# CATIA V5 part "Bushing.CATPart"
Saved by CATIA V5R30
Part number: Bushing
Bounding box of the stored display mesh (mm): x -13.45 to 13.45, y 0 to 63, z -13.45 to 13.45
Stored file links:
  D:\PROJECTS\CATIA V56R 2020\Resources\Parts File\c14_catia_v5_6r2020_prt\c14-catia-v5-6r2020-figr-14-26 & 27\Part & Asm\Bushing.CATPart
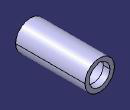
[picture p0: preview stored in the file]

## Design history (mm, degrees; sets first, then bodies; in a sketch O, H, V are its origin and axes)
Body1 (main body)
  Sketch1 on zx-plane, origin (0, 0, 0), H (-1, 0, 0), V (0, 0, 1)
    circle A1 centre (0, 0) radius 9.5
    circle A2 centre (0, 0) radius 13.45
    radius A1 = 9.5
    radius A2 = 13.45
  Pad1: profile Sketch1, direction (0, 1, 0), length 63
  Sketch2 on face of Pad1, origin (0, 63, 0), H (-1, 0, 0), V (0, 0, 1)
    line L1 (-1.5, 9.3808) -> (1.5, 9.3808)
    line L2 (1.5, 9.3808) -> (1.5, 10.1808)
    line L3 (1.5, 10.1808) -> (-1.5, 10.1808)
    line L4 (-1.5, 10.1808) -> (-1.5, 9.3808)
    point P2 (1.5, 9.3808)
    reference projected circle E1 centre (0, 0) radius 9.5 from edge of Pad1
    length L3 = 3
    length L2 = 0.8
    distance V L4 = 1.5
    horizontal: L1 H, L3 H
    vertical: L2 V, L4 V
    coincidence: P2 E1
  Pocket1: profile Sketch2, direction (0, -1, 0), through (limit type 6)
  Sketch3 on xy-plane, origin (0, 0, 0), H (1, 0, 0), V (0, 1, 0)
    line L1 (9.5, 57) -> (10.3, 57)
    line L2 (10.3, 57) -> (10.3, 49)
    line L3 (10.3, 49) -> (9.5, 49)
    line L4 (9.5, 49) -> (9.5, 57)
    reference projected line E1 (13.45, 63) -> (-13.45, 63) from edge of Pad1
    length L2 = 8
    length L1 = 0.8
    distance L3 E1 = 14
    distance V L4 = 9.5
    horizontal: L1 H, L3 H
    vertical: L2 V, L4 V
  Groove1: profile Sketch3, axis axis of face of Pad1, angle 360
